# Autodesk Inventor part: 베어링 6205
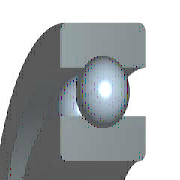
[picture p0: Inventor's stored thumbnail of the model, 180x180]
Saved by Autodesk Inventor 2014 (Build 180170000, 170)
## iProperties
Created: 2015-10
Part Number: 베어링 6205
Material: 강, 연강
Description: 깊은 그루브 볼 베어링
Document SubType Name: Modeling
Standard: KS B 2023
Designer: mdu
Standards Organization: KS
Language: ko-KR
Size Designation: 6205 - 25 x 52 x 15
Categories: <MemberInstance><Categories><Category DisplayName="샤프트 부품" InternalName="7f7aeb1f-a693-4053-b835-cee3144e0d98" Mnemonic="SHFT"><Category DisplayName="베어링" Inter
Density: 1 g/cm^3
Appearance: Yellow
IsCustomPart: 1
Author: mdu
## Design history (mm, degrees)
sketch "스케치" dims "d0" = 7.02 (= -0.26 x WD + 0.26 x BD)
  geometry: L1 (3.99, 19.25)-(11.01, 19.25); L2 (7.5, 19.25)-(7.5, 15.74); L3 (7.5, 19.25)-(7.5, 22.76); L4 (4.892, 16.901)-(0, 16.901); L5 (0, 12.5)-(15, 12.5); L6 (4.892, 21.599)-(0, 21.599); L7 (0, 26)-(15, 26); L8 (15, 12.5)-(15, 16.901); L9 (10.108, 16.901)-(15, 16.901); L10 (10.108, 21.599)-(15, 21.599); L11 (15, 26)-(15, 21.599); L12 (-1.4, 0)-(8.4, 0) reference; L13 (0, -0.3)-(0, 5.3) reference
  constraints: 22 end point, 4 point on line, 2 collinear, 2 perpendicular, 2 symmetric about line, 1 midpoint, 1 parallel, 14 other
  dimensions: "d9" = 25 diameter of L5 L12 (= WD); "d11" = 52 diameter of L7 L12 (= BD); "d12" = 15 distance between parallel lines of L8 L13 (= KB); "d13" = 33.802 diameter of L9 L12 (= 0.326 x BD + 0.674 x WD)
revolve "본체" stored, may be unused: angle "d6" = 90 deg
revolve "볼" stored, may be unused: angle "d7" = 90 deg
pattern_circular "IDS_ARRAYBALL[SIMPL:T]" dims angle "d3" = 360 deg
body "Solid1"
fillet "모깎기1" dims "d1" = 1 (= KRS)
other parameters: "WD" = 25 [user parameter; used in 5 equation terms], "BD" = 52 [user parameter; used in 5 equation terms], "KB" = 15 [user parameter; used in 1 equation term], "KRS" = 1 [user parameter; used in 1 equation term], "d4" = 0, "d5" = 0, "d8" = 0, "d14" = 0, "d15" = 0, "BBA" = 0 [user parameter], "BC0" = 7800000 [user parameter], "BC" = 1.4e+07 [user parameter], "BR" = 26 (= 0.5 x BD) [user parameter], "WR" = 12.5 (= 0.5 x WD) [user parameter]
